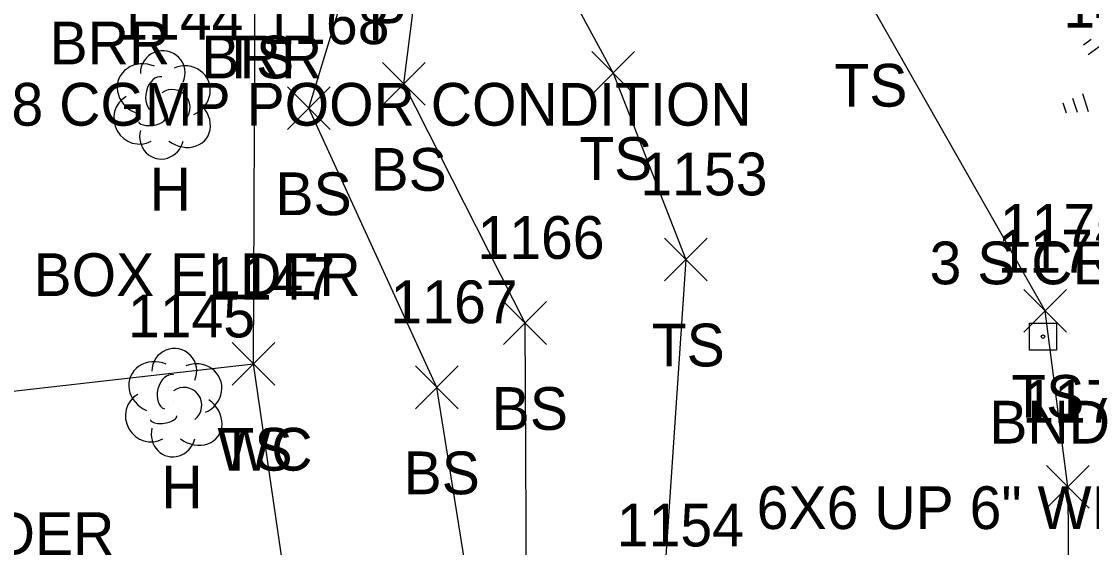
# Model space of a CAD drawing. Extents: x 1761340 to 1763889, y 696770 to 706023.
# Drawn here: x 1761564.7 to 1761614.7, y 700807 to 700831.6 of the extents above; entities that cross this region are included whole.
import ezdxf

# ---------------------------------------------------------------- set-up
doc = ezdxf.new("R2010")
doc.units = 0
for name, color, linetype in [('D_A', 7, 'Continuous'), ('D_C', 7, 'Continuous'), ('L_A', 7, 'Continuous'), ('L_C', 7, 'Continuous'), ('L_I', 7, 'Continuous'), ('L_TIC', 7, 'Continuous'), ('LAWE', 7, 'Continuous'), ('LELB', 7, 'Continuous'), ('LTC', 7, 'Continuous'), ('LTD', 7, 'Continuous'), ('M_A', 7, 'Continuous'), ('M_C', 7, 'Continuous'), ('M_I', 7, 'Continuous'), ('MHBP', 7, 'Continuous')]:
    doc.layers.add(name, color=color, linetype=linetype)

msp = doc.modelspace()

# ---------------------------------------------------------------- linework, layer by layer
at = {"layer": 'L_TIC'}
for points in [[(1761591.344, 700828.236), (1761593.344, 700830.236)], [(1761593.344, 700828.236), (1761591.344, 700830.236)], [(1761581.546, 700827.727), (1761583.546, 700829.727)], [(1761583.546, 700827.727), (1761581.546, 700829.727)], [(1761577.1, 700826.586), (1761579.1, 700828.586)], [(1761579.1, 700826.586), (1761577.1, 700828.586)], [(1761594.734, 700819.511), (1761596.734, 700821.511)], [(1761596.734, 700819.511), (1761594.734, 700821.511)], [(1761611.551, 700817.108), (1761613.551, 700819.108)], [(1761613.551, 700817.108), (1761611.551, 700819.108)], [(1761587.217, 700816.541), (1761589.217, 700818.541)], [(1761589.217, 700816.541), (1761587.217, 700818.541)], [(1761574.514, 700814.635), (1761576.514, 700816.635)], [(1761576.514, 700814.635), (1761574.514, 700816.635)], [(1761574.514, 700814.635), (1761576.514, 700816.635)], [(1761576.514, 700814.635), (1761574.514, 700816.635)], [(1761583.094, 700813.53), (1761585.094, 700815.53)], [(1761585.094, 700813.53), (1761583.094, 700815.53)], [(1761612.605, 700808.874), (1761614.605, 700810.874)], [(1761614.605, 700808.874), (1761612.605, 700810.874)]]:
    msp.add_lwpolyline(points, dxfattribs=at)
at = {"layer": 'LAWE'}
msp.add_lwpolyline([(1761514.71, 700872.069), (1761528.127, 700853.52), (1761542.133, 700836.591), (1761554.226, 700813.207), (1761575.514, 700815.635)], dxfattribs=at)
at = {"layer": 'LELB'}
for points in [[(1761577.539, 700801.73), (1761575.514, 700815.635), (1761575.59, 700833.986), (1761577.556, 700840.879), (1761581.517, 700842.64), (1761585.93, 700841.056), (1761592.344, 700829.236), (1761595.734, 700820.511), (1761594.635, 700804.09)], [(1761613.605, 700809.874), (1761612.551, 700818.108), (1761604.278, 700832.663), (1761606.418, 700841.276), (1761598.304, 700842.704)], [(1761610.621, 700781.935), (1761590.608, 700792.381), (1761586.211, 700801.285), (1761584.094, 700814.53), (1761578.1, 700827.586), (1761581.934, 700840.174), (1761583.885, 700839.339)], [(1761611.543, 700784.306), (1761591.202, 700796.53), (1761588.305, 700801.978), (1761588.217, 700817.541), (1761582.546, 700828.727), (1761583.885, 700839.339)], [(1761613.605, 700809.874), (1761613.704, 700794.244)]]:
    msp.add_lwpolyline(points, dxfattribs=at)
at = {"layer": 'LTC'}
for p, q in [((1761614.344, 700830.559), (1761614.699, 700830.817)), ((1761614.554, 700830.094), (1761615.083, 700830.478)), ((1761613.377, 700827.838), (1761613.529, 700827.37)), ((1761613.832, 700828.055), (1761614.044, 700827.403)), ((1761614.288, 700828.272), (1761614.559, 700827.436))]:
    msp.add_line(p, q, dxfattribs=at)
at = {"layer": 'LTD'}
for p, q in [((1761571.223, 700827.801), (1761571.223, 700827.801)), ((1761571.223, 700827.801), (1761571.223, 700827.801)), ((1761571.765, 700813.867), (1761571.765, 700813.867)), ((1761571.765, 700813.867), (1761571.765, 700813.867))]:
    msp.add_line(p, q, dxfattribs=at)
for centre in [(1761571.269, 700829.235), (1761571.811, 700815.301)]:
    msp.add_arc(centre, 1.047, 335.5272, 180.9563, dxfattribs=at)
for centre, major_axis, ratio, start_param, end_param in [((1761570.431, 700828.467), (1.21, -0.512), 0.895232, 1.570796, 4.712389), ((1761572.264, 700828.384), (-1.141, -0.483), 0.949671, 1.570796, 4.712389), ((1761571.014, 700828.259), (-0.208, -0.792), 0.645439, 3.141593, 6.283185), ((1761571.723, 700827.634), (-0.5, 0.667), 0.989748, 3.141593, 6.283185), ((1761570.139, 700827.092), (0.584, -1.042), 0.959034, 3.141593, 6.283185), ((1761572.223, 700826.967), (-1.09, 0.792), 0.841452, 1.570796, 4.712389), ((1761570.764, 700827.051), (-0.625, -0.083), 0.423636, 0, 3.141593), ((1761571.223, 700826.301), (0.265, 1.061), 0.942809, 1.570796, 4.712389), ((1761570.973, 700814.533), (1.21, -0.512), 0.895232, 1.570796, 4.712389), ((1761572.806, 700814.45), (-1.141, -0.483), 0.949671, 1.570796, 4.712389), ((1761571.556, 700814.325), (-0.208, -0.792), 0.645439, 3.141593, 6.283185), ((1761572.265, 700813.7), (-0.5, 0.667), 0.989748, 3.141593, 6.283185), ((1761570.681, 700813.158), (0.584, -1.042), 0.959034, 3.141593, 6.283185), ((1761572.765, 700813.033), (-1.09, 0.792), 0.841452, 1.570796, 4.712389), ((1761571.306, 700813.116), (-0.625, -0.083), 0.423636, 0, 3.141593), ((1761571.765, 700812.367), (0.265, 1.061), 0.942809, 1.570796, 4.712389)]:
    msp.add_ellipse(centre, major_axis=major_axis, ratio=ratio, start_param=start_param, end_param=end_param, dxfattribs=at)
at = {"layer": 'MHBP'}
msp.add_lwpolyline([(1761611.823, 700817.527), (1761613.073, 700817.527), (1761613.073, 700816.277), (1761611.823, 700816.277)], close=True, dxfattribs=at)
msp.add_circle((1761612.448, 700816.902), 0.0833, dxfattribs=at)

# ---------------------------------------------------------------- texts
at = {"layer": 'D_A'}
msp.add_text('P', height=2, dxfattribs=at).set_placement((1761580.892, 700830.771))
at = {"layer": 'D_C'}
msp.add_text('18 CGMP POOR CONDITION', height=2, dxfattribs=at).set_placement((1761562.704, 700826.771))
at = {"layer": 'L_A'}
for s, p in [('BRR', (1761565.974, 700829.637)), ('BRR', (1761573.079, 700828.986)), ('TS', (1761574, 700828.986)), ('TS', (1761602.687, 700827.663)), ('TS', (1761590.753, 700824.236)), ('BS', (1761580.987, 700823.727)), ('H', (1761570.656, 700822.801)), ('BS', (1761576.541, 700822.586)), ('TS', (1761594.144, 700815.511)), ('TS', (1761610.961, 700813.108)), ('BS', (1761586.658, 700812.541)), ('WC', (1761573.821, 700810.635)), ('TS', (1761573.924, 700810.635)), ('BS', (1761582.535, 700809.53)), ('H', (1761571.198, 700808.867))]:
    msp.add_text(s, height=2, dxfattribs=at).set_placement(p)
at = {"layer": 'L_C'}
for s, p in [('3 S CEDARS', (1761607.142, 700819.351)), ('2 M. BOX ELDER', (1761559.278, 700818.801)), ('M. BOX ELDER', (1761549.984, 700806.69))]:
    msp.add_text(s, height=2, dxfattribs=at).set_placement(p)
at = {"layer": 'L_I'}
for s, p in [('1446', (1761613.401, 700831.351)), ('1144', (1761569.097, 700830.801)), ('1168', (1761575.927, 700830.586)), ('1153', (1761593.609, 700823.511)), ('1175', (1761610.425, 700821.108)), ('1166', (1761585.989, 700820.541)), ('1147', (1761573.389, 700818.635)), ('1147', (1761573.389, 700818.635)), ('1167', (1761581.921, 700817.53)), ('1145', (1761569.639, 700816.867)), ('1174', (1761611.479, 700812.874)), ('1154', (1761592.509, 700807.09))]:
    msp.add_text(s, height=2, dxfattribs=at).set_placement(p)
at = {"layer": 'M_A'}
msp.add_text('BND', height=2, dxfattribs=at).set_placement((1761609.936, 700811.902))
at = {"layer": 'M_C'}
msp.add_text('6X6 UP 6" WITH V', height=2, dxfattribs=at).set_placement((1761599.054, 700807.902))
at = {"layer": 'M_I'}
msp.add_text('1173', height=2, dxfattribs=at).set_placement((1761610.322, 700819.902))

doc.saveas('drawing.dxf')
